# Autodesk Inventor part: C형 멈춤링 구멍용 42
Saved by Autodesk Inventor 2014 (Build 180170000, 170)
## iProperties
Created: 2025-12
Part Number: C형 멈춤링 구멍용 42
Material: 일반
Document SubType Name: Modeling
Designer: dg
Density: 1 g/cm^3
Appearance: 기본값
Author: dg
Author: jhkim
Description: 리테이닝 링(C형)
Creation Date: 2025-11-19
Sending System: Autodesk Inventor 2026
Preprocessor: ST-DEVELOPER v20.1
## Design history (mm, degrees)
node "C형 멈춤링 구멍용 421"
body "Solid1"
node "기준1"
